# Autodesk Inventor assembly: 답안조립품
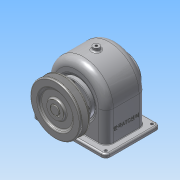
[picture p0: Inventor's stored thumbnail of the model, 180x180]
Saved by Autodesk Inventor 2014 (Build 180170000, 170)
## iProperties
Created: 2016-01
Part Number: 답안조립품
Document SubType Name: Assembly
Designer: user
Author: user
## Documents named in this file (16)
- C:\Users\user\Desktop\460105V1025\답안조립품.iam
- C:\Users\user\Desktop\460105V1025\V-벨트풀리.ipt
- C:\Users\user\Desktop\460105V1025\뒤커버.ipt
- C:\Users\user\Desktop\460105V1025\멈춤나사 - M4x10.ipt
- C:\Users\user\Desktop\460105V1025\베어링 6203.ipt
- C:\Users\user\Desktop\460105V1025\본체.ipt
- C:\Users\user\Desktop\460105V1025\볼트 M3 x 8.ipt
- C:\Users\user\Desktop\460105V1025\볼트 M3 x 10.ipt
- C:\Users\user\Desktop\460105V1025\부시1.ipt
- C:\Users\user\Desktop\460105V1025\부시2.ipt
- C:\Users\user\Desktop\460105V1025\스퍼기어.ipt
- C:\Users\user\Desktop\460105V1025\앞커버.ipt
- C:\Users\user\Desktop\460105V1025\오일씰 28 40 8.ipt
- C:\Users\user\Desktop\460105V1025\축.ipt
- C:\Users\user\Desktop\460105V1025\키 - 5 x 5 x 18.ipt
- C:\Users\user\Desktop\460105V1025\키 - 6 x 6 x 22.ipt
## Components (9 placed, 3 different names)
1. V-벨트풀리:1 — 각도:4
2. ISO 4762 M3 x 8:1
3. ISO 4762 M3 x 8:2
4. ISO 4762 M3 x 8:3
5. ISO 4762 M3 x 8:4
6. ISO 4762 M3 x 10:1
7. ISO 4762 M3 x 10:2
8. ISO 4762 M3 x 10:3
9. ISO 4762 M3 x 10:4
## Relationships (1: Angle 1)
- 각도:4 [Angle]: V-벨트풀리:1
